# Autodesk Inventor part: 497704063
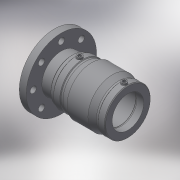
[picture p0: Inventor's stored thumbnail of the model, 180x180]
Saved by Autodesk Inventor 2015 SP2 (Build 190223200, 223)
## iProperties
Created: 2017-06
Part Number: 497704063
Material: Generic
Description: PLASSON PE CAST IRON SPIGOT COUPLER TRANSITION 225-200
Document SubType Name: Modeling
Designer: KIM
Mass: 55.0731 g
Surface Area: 148.067 cm^2
Volume: 55.0731 cm^3
Density: 1 g/cm^3
Appearance: Default
Author: KIM
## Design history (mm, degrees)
derived "497704.ipt"
feature "Solid1::497704.ipt"
tag "TaggingFeature1"
body "Solid1"
other parameters: "d13" = 119, "d14" = 17.6296, "d15" = 57, "d16" = 57, "d17" = 59.85, "d18" = 63, "d19" = 3.52592, "d20" = 168 deg, "d22" = 97.76, "d23" = 104, "d24" = 94.8272, "d25" = 135 deg, "d26" = 47.6, "d27" = 135 deg, "d29" = 57, "d35" = 15, "d39" = 5 deg, "d45" = 4, "d46" = 14, "d47" = 0, "d50" = 3, "d51" = 0, "d52" = 19.38, "d53" = 4.845, "d55" = 0.1, "d56" = 92.56, "d58" = 98, "d60" = 43, "d62" = 3.12, "d65" = 2.08, "d68" = 104, "d69" = 165, "d71" = 6.66667, "d72" = 83.304, "d73" = 12, "d74" = 18, "d75" = 62.5, "d77" = 0, "d79" = 360 deg, "d_" = 63, "L_" = 217, "L_1" = 57, "D_1" = 104, "A_" = 57, "d_2" = 12, "L_2" = 98, "H_" = 109, "D_" = 165, "d_1" = 43, "S_" = 18, "D_p" = 125
